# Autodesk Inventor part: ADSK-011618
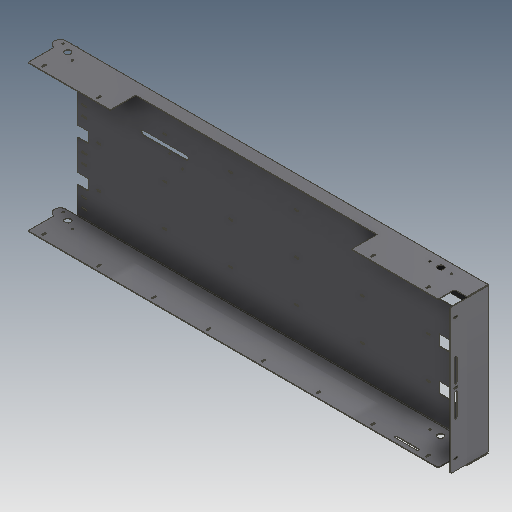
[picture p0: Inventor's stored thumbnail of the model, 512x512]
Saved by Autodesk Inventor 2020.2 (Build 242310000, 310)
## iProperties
Created: 2000-02
Part Number: ADSK-011618
Material: Pearson HRS
Document SubType Name: Tôlerie
Designer: sspink
Density: 7.83 g/cm^3
Sheet Metal Rule: Stahlblech 1.0312 - DC05 -   3.0 mm
Appearance: Métal - Acier
Mass: 45021.9 g
Surface Area: 38684.9 cm^2
Volume: 5749.93 cm^3
Flat Pattern Width: 102.807 cm
Flat Pattern Length: 215.579 cm
Flat Pattern Area: 22163 cm^2
Sheet Metal Width: 1028,072 mm
Sheet Metal Length: 2155,786 mm
Sheet Metal Area: 2216302,371 mm^2
Control State: 0
Master: False
Checked Out: False
Shininess: 25.0
Length Units: 11269
Angle Units: 11279
Time Units: 11290
Mass Units: 11283
Length Display Precision: 3
Angle Display Precision: 2
Compacted: True
Cutlength: 23.25
Material Desc: Material Description goes here
Material_Number: Pearson
G_L: 1028,1x2155,8 mm
Thickness: 3,000 mm
Dimensions: 678,5x180x1981 mm
Mass: 5,75 kg
Semi finished: Stahlblech 1.0312 - DC05 -   3.0 mm
VLT_Material: 1.0312 DC05
Density: 0.0
Volumn: 0.0
Area: 0.0
PropertySet Name: Model Information
Author: sspink
Revision Number: -
Title: ADSK-011618
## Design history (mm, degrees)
node "Solide1"
derived "ADSK-011617.ipt"
  workplane "Arbeitsebene3"
  workplane "Arbeitsebene4"
node "FonctionRepérage2"
feature "Solide1::ADSK-011617.ipt" dims "d0" = 10
node "FlatPattern"
node "Corps solides"
node "Corps surfaciques"
feature "Extrusion_mise_à_plat2" dims "d0" = 3 (derived)
other parameters: "Thickness" = 3 (derived), "BendRadius" = 3 (= Thickness), "BendReliefWidth" = 3 (= Thickness), "BendReliefDepth" = 1.5 (= 0.5 x Thickness), "CornerReliefSize" = 12 (= 4 x Thickness), "SeamGap" = 0.00508, "MinimumRemnant" = 6 (= 2 x Thickness), "TransitionRadius" = 3 (= BendRadius), "TailleRayonJacobi" = 3 (= BendRadius), "TailleJeu" = 3 (= Thickness)
